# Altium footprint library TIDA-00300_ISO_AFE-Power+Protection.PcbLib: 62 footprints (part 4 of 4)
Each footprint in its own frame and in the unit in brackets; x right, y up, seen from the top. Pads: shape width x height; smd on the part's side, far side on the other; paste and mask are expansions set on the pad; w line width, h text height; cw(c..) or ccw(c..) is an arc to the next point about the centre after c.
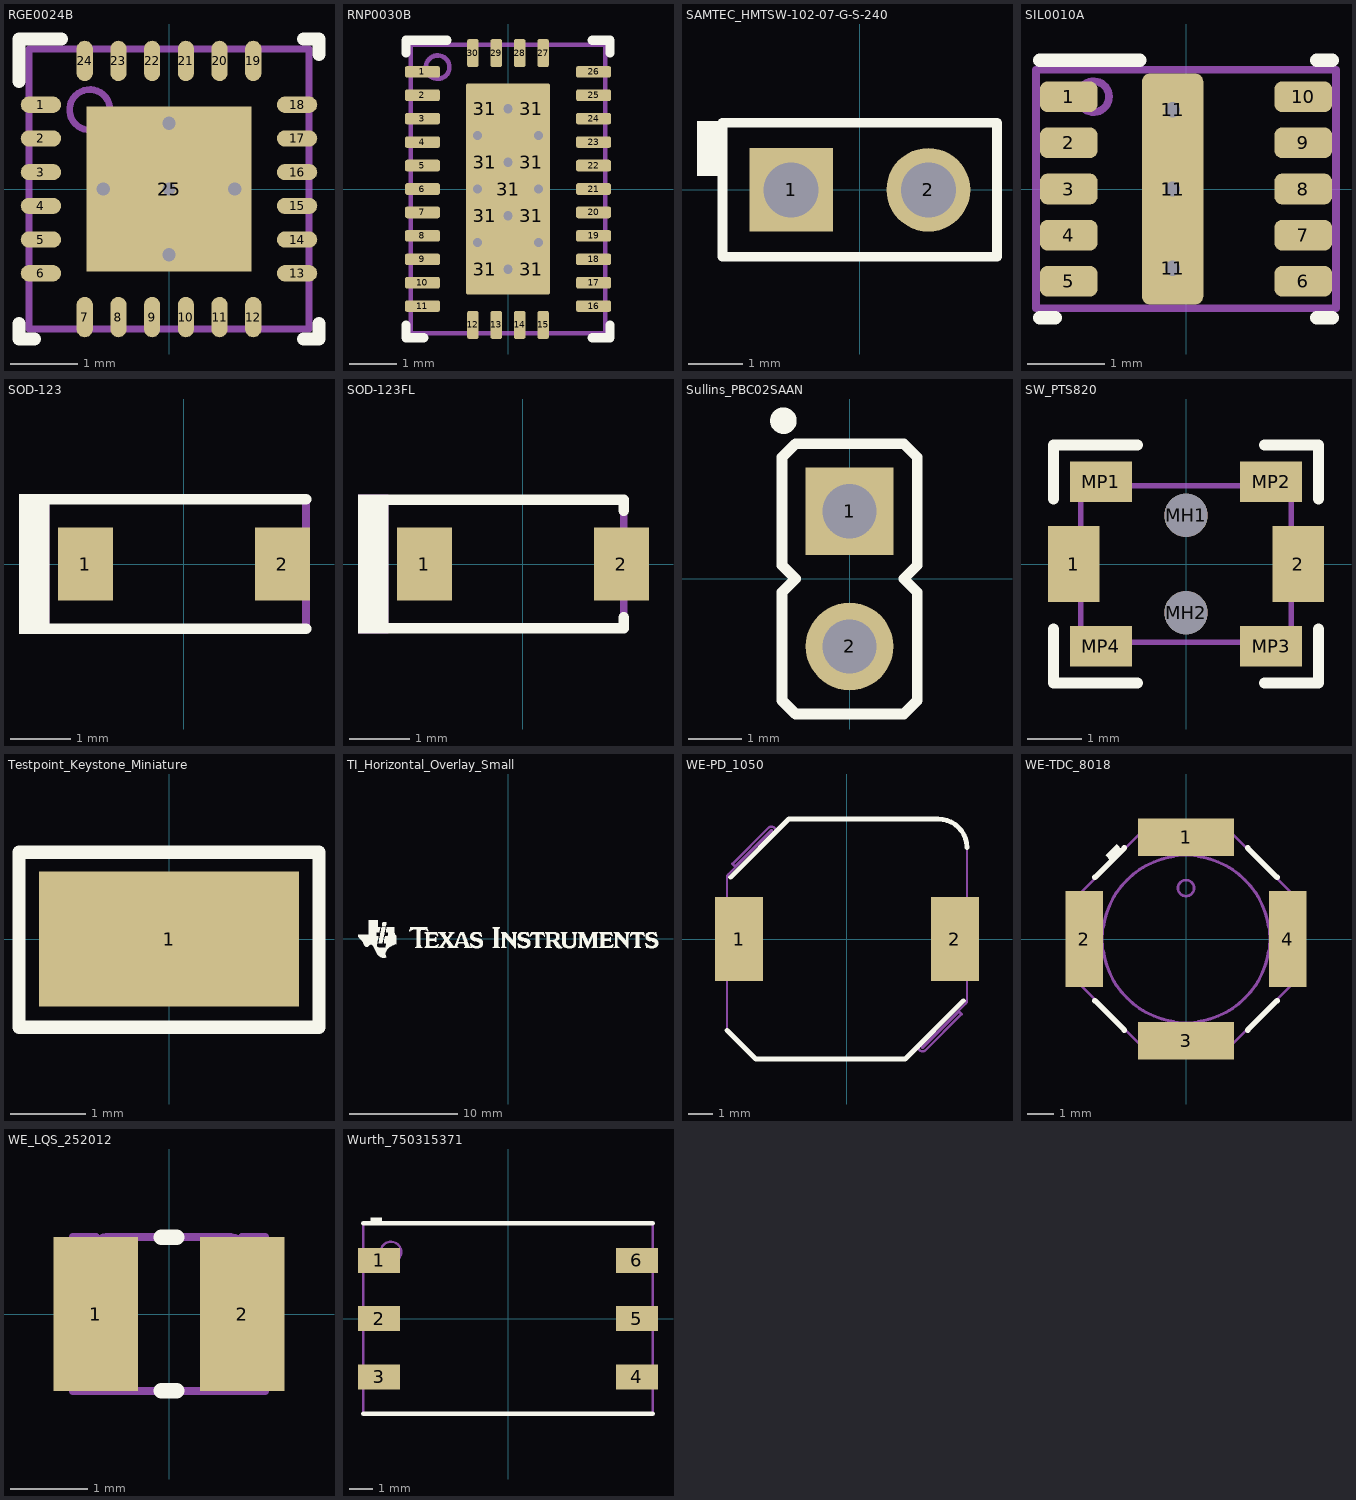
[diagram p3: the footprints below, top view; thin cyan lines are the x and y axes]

## RGE0024B [mm] "QFN, 24-Leads, Body 4x4mm, Pitch 0.5mm, Thermal Pad 2.45x2.45mm, TI Recommended"
height 1
pads (25):
  oval 0.6x0.24 smd: 1(-1.9,1.25) 2(-1.9,0.75) 3(-1.9,0.25) 4(-1.9,-0.25) 5(-1.9,-0.75) 6(-1.9,-1.25) 13(1.9,-1.25) 14(1.9,-0.75) 15(1.9,-0.25) 16(1.9,0.25) 17(1.9,0.75) 18(1.9,1.25)
  oval 0.24x0.6 smd: 7(-1.25,-1.9) 8(-0.75,-1.9) 9(-0.25,-1.9) 10(0.25,-1.9) 11(0.75,-1.9) 12(1.25,-1.9) 19(1.25,1.9) 20(0.75,1.9) 21(0.25,1.9) 22(-0.25,1.9) 23(-0.75,1.9) 24(-1.25,1.9)
  rect 2.45x2.45 smd paste-1.225: 25(0,0)
via 0.975,0 diameter 0.5 hole 0.2
via 0,0.975 diameter 0.5 hole 0.2
via 0,0 diameter 0.5 hole 0.2
via 0,-0.975 diameter 0.5 hole 0.2
via -0.975,0 diameter 0.5 hole 0.2
Top Overlay:
  lines w0.2: -2.225,-2 -2.225,-2.225 -2,-2.225 ; -2.225,1.6 -2.225,2.225 -1.6,2.225 ; 2,-2.225 2.225,-2.225 2.225,-2 ; 2,2.225 2.225,2.225 2.225,2
Top Paste:
  rectangle: 0.1,0.1 1.184,1.184
  rectangle: 0.1,-1.184 1.184,-0.1
  region: -0.1,1.184 -1.184,1.184 -1.184,0.1 -0.1,0.1
  region: -0.1,-0.1 -1.184,-0.1 -1.184,-1.184 -0.1,-1.184
Mechanical 5:
  circle w0.1: c-1.175,1.175 r0.3
  lines w0.1: -2.075,-2.075 2.075,-2.075 2.075,2.075 -2.075,2.075 -2.075,-2.075
  text ".Designator" at -1.27,-0.762 h0.51
3D body: height 1, standoff 0, extent -2.075,-2.075 2.075,2.075
3D body: height 1.01, standoff 0.5, extent -1.474,0.876 -0.876,1.474

## RNP0030B [mm] "QFN, 30-Leads, Body 6x4mm, Pitch 0.5mm, Thermal Pad 1.8x4.5mm"
height 0.8
pads (39):
  rrect40% 0.75x0.25 smd: 1(-1.825,2.5) 2(-1.825,2) 3(-1.825,1.5) 4(-1.825,1) 5(-1.825,0.5) 6(-1.825,0) 7(-1.825,-0.5) 8(-1.825,-1) 9(-1.825,-1.5) 10(-1.825,-2) 11(-1.825,-2.5) 16(1.825,-2.5) 17(1.825,-2) 18(1.825,-1.5) 19(1.825,-1) 20(1.825,-0.5) 21(1.825,0) 22(1.825,0.5) 23(1.825,1) 24(1.825,1.5) 25(1.825,2) 26(1.825,2.5)
  rrect40% 0.25x0.6 smd: 12(-0.75,-2.9) 13(-0.25,-2.9) 14(0.25,-2.9) 15(0.75,-2.9) 27(0.75,2.9) 28(0.25,2.9) 29(-0.25,2.9) 30(-0.75,2.9)
  rrect50% 0.8x0.94 on Top Paste: 31(-0.5,-1.71) 31(-0.5,-0.57) 31(-0.5,0.57) 31(-0.5,1.71) 31(0.5,-1.71) 31(0.5,-0.57) 31(0.5,0.57) 31(0.5,1.71)
  rrect5% 1.8x4.5 smd paste-3: 31(0,0)
via 0.65,0 diameter 0.5 hole 0.2
via 0.65,1.14 diameter 0.5 hole 0.2
via -0.65,1.14 diameter 0.5 hole 0.2
via 0,1.71 diameter 0.5 hole 0.2
via 0,0.57 diameter 0.5 hole 0.2
via 0,-0.57 diameter 0.5 hole 0.2
via 0,-1.71 diameter 0.5 hole 0.2
via -0.65,-1.14 diameter 0.5 hole 0.2
via 0.65,-1.14 diameter 0.5 hole 0.2
via -0.65,0 diameter 0.5 hole 0.2
Top Overlay:
  lines w0.2: -2.175,-2.9 -2.175,-3.175 -1.8,-3.175 ; -2.175,2.9 -2.175,3.175 -1.3,3.175 ; 1.8,-3.175 2.175,-3.175 2.175,-2.9 ; 1.8,3.175 2.175,3.175 2.175,2.9
Mechanical 5:
  circle w0.1: c-1.5,2.6 r0.25
  lines w0.1: -2.075,-3.075 -2.075,3.075 2.075,3.075 2.075,-3.075 -2.075,-3.075
  text ".Designator" at 0.595,0.304 h0.51
3D body "RNP0030B.stp": height 0.8, standoff 0, extent -2,-3 2,3

## SAMTEC_HMTSW-102-07-G-S-240 [mm] "Header, 2.54mm, 2x1, TH"
height 8.58
pads (2):
  rect 1.55x1.55 hole 1.02: 1(-1.27,0)
  round 1.55 hole 1.02: 2(1.27,0)
Top Overlay:
  region: -2.54,1.27 -3.012,1.27 -3.012,0.254 -2.54,0.254
  lines w0.178: -2.54,-1.24 -2.54,1.24 2.54,1.24 2.54,-1.24 -2.54,-1.24
Mechanical 5:
  lines w0.127: -2.54,-1.24 2.54,-1.24 2.54,1.24 -2.54,1.24 -2.54,-1.24
  text ".Designator" at -0.758,-0.222 h0.51
3D body "Samtec-HMTSW-102-07-G-S-240.stp": height 8.64, standoff -2.29, extent -2.54,-1.27 2.54,1.27

## SIL0010A [mm] "MicoSiP, TI recommended land pattern"
height 1.578
pads (14):
  rrect50% 0.75x0.4 smd paste-0.05 mask-0.05: 1(-1.525,1.2) 2(-1.525,0.6) 3(-1.525,0) 4(-1.525,-0.6) 5(-1.525,-1.2) 6(1.525,-1.2) 7(1.525,-0.6) 8(1.525,0) 9(1.525,0.6) 10(1.525,1.2)
  rrect50% 0.7x0.833 on Top Paste: 11(-0.175,-1.03) 11(-0.175,0) 11(-0.175,1.03)
  rrect25% 0.8x3 smd paste-0.5 mask-0.05: 11(-0.175,0)
via -0.175,0 diameter 0.5 hole 0.2
via -0.175,1.03 diameter 0.5 hole 0.2
via -0.175,-1.03 diameter 0.5 hole 0.2
Top Overlay:
  lines w0.178: -1.9,-1.675 -1.7,-1.675 ; -1.9,1.675 -0.6,1.675 ; 1.7,-1.675 1.9,-1.675 ; 1.7,1.675 1.9,1.675
Mechanical 5:
  circle w0.1: c-1.2,1.2 r0.2
  lines w0.1: -1.95,-1.55 -1.95,1.55 1.95,1.55 1.95,-1.55 -1.95,-1.55
  text ".Designator" at -2.069,-0.403 h0.51
3D body "SIL0010A.stp": height 1.49, standoff 0, extent -1.9,-1.5 1.9,1.5

## SOD-123 [mm] "On Semi recommended land pattern"
height 1.35
pads (2):
  rect 0.915x1.22 smd: 1(-1.637,0) 2(1.637,0)
Top Overlay:
  rectangle: -2.743,-1.168 -2.235,1.168
  lines w0.178: -2.413,-1.079 2.032,-1.079 ; -2.413,1.079 2.032,1.079
Mechanical 5:
  rectangle: -2.743,-1.168 -2.235,1.168
  lines w0.127: -2.413,-1.079 2.032,-1.079 2.032,1.079 -2.413,1.079
  text ".Designator" at 0.377,0.12 h0.51
3D body "SOD-123.stp": height 1.35, standoff 0, extent -1.932,-0.9 1.932,0.9

## SOD-123FL [mm] "Copied from SOD-123"
height 0.991
pads (2):
  rect 0.915x1.22 smd: 1(-1.637,0) 2(1.637,0)
Top Overlay:
  rectangle: -2.743,-1.156 -2.235,1.156
  lines w0.178: -2.438,-1.067 1.676,-1.067 1.676,-0.889 ; -2.438,1.067 1.676,1.067 1.676,0.889
Mechanical 5:
  rectangle: -2.743,-1.156 -2.235,1.156
  lines w0.127: -2.438,-1.067 1.676,-1.067 1.676,1.067 -2.438,1.067
  text ".Designator" at -0.032,-0.276 h0.51
3D body "SOD-123FL.stp": height 1, standoff 0, extent -1.9,-0.9 1.9,0.9

## Sullins_PBC02SAAN [mm] "Sullins 100mil, 1x2, 230 mil above insulator"
height 8.382
pads (2):
  rect 1.65x1.65 hole 1.016: 1(0,1.27)
  round 1.65 hole 1.016: 2(0,-1.27)
Top Overlay:
  circle w0.25: c-1.245,2.972 r0.125
  lines w0.2: -1.27,-2.286 -1.27,-0.254 -1.016,0 -1.27,0.254 -1.27,2.286 -1.016,2.54 1.016,2.54 1.27,2.286 1.27,0.254 1.016,0 1.27,-0.254 1.27,-2.286 1.016,-2.54 -1.016,-2.54 -1.27,-2.286
Mechanical 5:
  lines w0.1: -1.27,-2.286 -1.016,-2.54 1.016,-2.54 1.27,-2.286 1.27,-0.254 1.016,0 1.27,0.254 1.27,2.286 1.016,2.54 -1.016,2.54 -1.27,2.286 -1.27,0.254 -1.016,0 -1.27,-0.254 -1.27,-2.286
  text ".Designator" at -0.533,-0.203 h0.51
3D body: height 2.54, standoff 0, extent -1.27,-2.54 1.27,2.54
3D body: height 8.38, standoff -3.05, extent -0.317,-1.587 0.317,-0.953
3D body: height 8.38, standoff -3.05, extent -0.317,0.953 0.317,1.587

## SW_PTS820 [mm] "SMT, 2-Leads, Body 3.9x2.9mm"
height 2
pads (8):
  rect 0.95x1.4 smd: 1(-2.075,0) 2(2.075,0)
  round 0.8 hole 0.8 unplated: MH1(0,0.9) MH2(0,-0.9)
  rect 1.15x0.75 smd: MP1(-1.575,1.525) MP2(1.575,1.525) MP3(1.575,-1.525) MP4(-1.575,-1.525)
Top Overlay:
  lines w0.2: -2.45,-1.2 -2.45,-2.2 -0.9,-2.2 ; -2.45,1.2 -2.45,2.2 -0.9,2.2 ; 1.45,-2.2 2.45,-2.2 2.45,-1.2 ; 1.45,2.2 2.45,2.2 2.45,1.2
Mechanical 5:
  lines w0.1: -1.95,-0.5 -1.982,-0.5 -2.157,-0.5 -2.25,-0.5 -2.25,0.5 -2.157,0.5 -1.982,0.5 -1.95,0.5 ; 1.95,-0.5 1.982,-0.5 2.157,-0.5 2.25,-0.5 2.25,0.5 2.157,0.5 1.982,0.5 1.95,0.5 ; -1.95,-1.45 -1.95,1.45 1.95,1.45 1.95,-1.45 -1.95,-1.45
  text ".Designator" at -0.267,-0.309 h0.51
3D body "PTS820.stp": height 2, standoff -0.5, extent -2.25,-1.45 2.25,1.45

## Testpoint_Keystone_Miniature [mil] "Miniature SMT test point"
height 90.55
pads (1):
  rect 135x70 smd: 1(0,0)
Top Overlay:
  lines w7: -78,-46 -78,-38 -78,45 -65,45 5,45 78,45 78,-46 -78,-46
Mechanical 5:
  lines w5: -78,-46 78,-46 78,45 5,45 -65,45 -78,45 -78,-38 -78,-46
  text ".Designator" at 35,10 h20
3D body "keystone_5015.stp": height 60.6, standoff 0.6, extent -52.5,-20 52.5,20

## TI_Horizontal_Overlay_Small [mm]
Top Overlay:
  drawing of 18 lines, arcs and shapes, not listed

## WE-PD_1050 [mm] "WERTH"
height 5
pads (2):
  rect 2x3.5 smd: 1(-4.5,0) 2(4.5,0)
Top Overlay:
  lines w0.2: -5,-3.8 -3.8,-5 -1.6,-5 2.384,-5 ; -4.85,2.575 -2.425,5 ; -2.384,5 1.6,5 3.8,5 cw(c3.8,3.8) 5,3.8 ; 2.425,-5 4.85,-2.575
Mechanical 5:
  lines w0.1: -5,-1.6 -5,-3.8 -3.8,-5 2.425,-5 4.85,-2.575 ; -5,-1.5 -5,1.5 -5,2.566 cw(c-4.83,2.566) -4.95,2.687 -3.137,4.5 ccw(c-3.151,4.514) -3.165,4.529 -4.671,3.022 -4.777,3.128 -3.271,4.635 cw(c-3.151,4.514) -3.03,4.394 ; -4.85,2.575 -2.425,5 3.8,5 cw(c3.8,3.8) 5,3.8 5,1.6 ; 3.03,-4.394 ccw(c3.151,-4.514) 3.271,-4.635 4.777,-3.128 4.671,-3.022 3.165,-4.529 cw(c3.151,-4.514) 3.137,-4.5 4.95,-2.687 ccw(c4.83,-2.566) 5,-2.566 5,-1.5 5,1.5
  text ".Designator" at -0.429,0.257 h0.51
3D body "7447714xx.stp": height 4.75, standoff -0.05, extent -5,-5 5,5

## WE-TDC_8018 [mm] "SMD, 4-Leads, Body 8x8mm"
height 2.1
pads (4):
  rect 3.6x1.4 smd: 1(0,3.8) 3(0,-3.8)
  rect 1.4x3.6 smd: 2(-3.8,0) 4(3.8,0)
Top Overlay:
  region: -2.806,2.909 -2.382,3.333 -2.594,3.546 -3.018,3.121
  lines w0.2: -3.4,-2.3 -2.3,-3.4 ; -3.4,2.3 -2.3,3.4 ; 2.3,-3.4 3.4,-2.3 ; 2.3,3.4 3.4,2.3
Mechanical 5:
  circle w0.1: c0,0 r3.125
  lines w0.1: -3.077,-0.45 ccw(c0,0) -0.45,-3.077 ; -3.077,0.45 cw(c0,0) -0.45,3.077 ; 0.45,-3.077 ccw(c0,0) 3.077,-0.45 ; 0.45,3.077 cw(c0,0) 3.077,0.45 ; -4,-1.657 -4,1.657 -1.657,4 1.657,4 4,1.657 4,-1.657 1.657,-4 -1.657,-4 -4,-1.657 ; -0.3,1.9 cw(c0,1.9) 0.3,1.9 cw(c0,1.9) -0.3,1.9
  text ".Designator" at -0.236,-0.765 h0.51
3D body "WE-TDC_8018.stp": height 1.79, standoff -0.01, extent -4,-4 4,4

## WE_LQS_252012 [mm] "SMD, 2-Leads, Body 2.5x2mm, Pitch 1.9mm"
height 1.2
pads (2):
  rect 1.1x2 smd: 1(-0.95,0) 2(0.95,0)
Top Overlay:
  lines w0.2: -0.1,-1 0.1,-1 ; -0.1,1 0.1,1
Mechanical 5:
  drawing of 172 lines, arcs and shapes, not listed
  text ".Designator" at 0.323,-0.352 h0.51
3D body "WE-LQS_252012.stp": height 1.2, standoff 0, extent -1.25,-1 1.25,1

## Wurth_750315371 [mm] "SMD, Body 12.6x8.3mm, Pitch 2.54mm"
height 4.1
pads (6):
  rect 1.83x1.09 smd: 1(-5.62,2.54) 2(-5.62,0) 3(-5.62,-2.54) 4(5.62,-2.54) 5(5.62,0) 6(5.62,2.54)
Top Overlay:
  region: -6,4.4 -6,4.2 -5.5,4.2 -5.5,4.4
  lines w0.2: -6.3,-4.15 6.3,-4.15 ; -6.3,4.15 6.3,4.15
Mechanical 5:
  circle w0.1: c-5.1,2.9 r0.45
  lines w0.1: -6.3,-4.15 -6.3,4.15 6.3,4.15 6.3,-4.15 -6.3,-4.15
  text ".Designator" at -1.9,-0.4 h0.51
3D body: height 4.1, standoff 0, extent -6.35,-4.2 6.35,4.2
3D body: height 4.11, standoff 4.1, extent -5.549,2.451 -4.651,3.349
